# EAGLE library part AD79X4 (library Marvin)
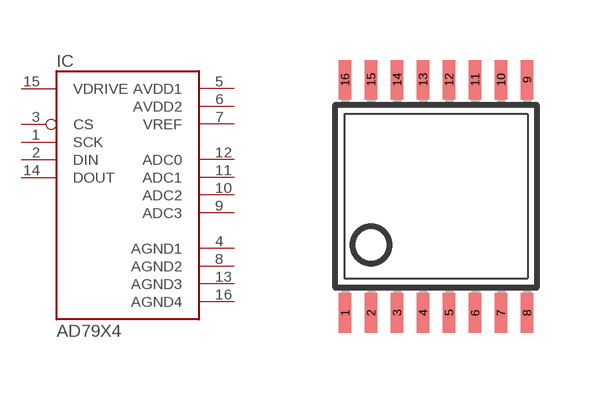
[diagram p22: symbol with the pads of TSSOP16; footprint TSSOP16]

Designator prefix IC

## AD79X4  [TSSOP16]
1  SCK
2  DIN
3  CS
4  AGND1
5  AVDD1
6  AVDD2
7  VREF
8  AGND2
9  ADC3
10  ADC2
11  ADC1
12  ADC0
13  AGND3
14  DOUT
15  VDRIVE
16  AGND4

## Footprint TSSOP16 (pad centres in mm)
smd 0.305 x 0.991: 1 -2.275,-2.918; 2 -1.625,-2.918; 3 -0.975,-2.918; 4 -0.325,-2.918; 5 0.325,-2.918; 6 0.975,-2.918; 7 1.625,-2.918; 8 2.275,-2.918; 9 2.275,2.918; 10 1.625,2.918; 11 0.975,2.918; 12 0.325,2.918; 13 -0.325,2.918; 14 -0.975,2.918; 15 -1.625,2.918; 16 -2.275,2.918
